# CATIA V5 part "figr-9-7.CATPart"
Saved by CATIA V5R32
Part number: Part2
Bounding box of the stored display mesh (mm): x -96.278 to 96.278, y -96.278 to 96.278, z -26.878 to 0
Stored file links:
  D:\PROJECTS\Project 2022\CATIA V5 6R 2022\Resources\Part Files\c09_catia_v5_6r2022_prt\c09_catia_v5_6r2022_prt\figr-9-7.CATPart
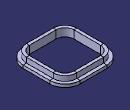
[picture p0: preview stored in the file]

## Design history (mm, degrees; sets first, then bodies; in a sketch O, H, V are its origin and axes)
Body1 (main body)
  Sketch1 on xy-plane, origin (0, 0, 0), H (1, 0, 0), V (0, 1, 0)
    point P1 (-75, 75)
    line L1 (-45, 75) -> (45, 75)
    line L2 (75, 45) -> (75, -45)
    line L3 (45, -75) -> (-45, -75)
    line L4 (-75, -45) -> (-75, 45)
    point P2 (75, 75)
    point P3 (75, -75)
    point P4 (-75, -75)
    axis line L5 (75, -75) -> (-75, 75)
    arc A1 centre (45, -45) radius 30 from (75, -45) to (45, -75) cw
    arc A2 centre (45, 45) radius 30 from (45, 75) to (75, 45) cw
    arc A3 centre (-45, 45) radius 30 from (-45, 75) to (-75, 45) ccw
    arc A4 centre (-45, -45) radius 30 from (-45, -75) to (-75, -45) cw
    distance P2 P3 = 150
    distance P3 P4 = 150
    radius A1 = 30
    radius A2 = 30
    radius A3 = 30
    radius A4 = 30
    horizontal: L1 H, L3 H
    vertical: L2 V, L4 V
    midpoint: O L5
    coincidence: L2 P3, L3 P3, L1 P2, L2 P2, L1 P1, L4 P1, L3 P4, L4 P4
    tangency: A1 L2, A1 L3, A2 L1, A2 L2, A3 L1, A3 L4, A4 L3, A4 L4
  Sketch2 on yz-plane, origin (0, 0, 0), H (0, 1, 0), V (0, 0, 1)
    point P1 (85, 0)
    line L1 (85, 0) -> (85, -16.8782)
    line L2 (85, -16.8782) -> (96.2781, -16.8782)
    line L3 (96.2781, -16.8782) -> (96.2781, -26.8782)
    line L4 (96.2781, -26.8782) -> (75, -26.8782)
    line L5 (75, -26.8782) -> (75, 0)
    point P6 (75, 0)
    line L6 (75, 0) -> (85, 0)
    reference projected point E1 (75, 0) from edge of Sketch1
    length L3 = 10
    length L6 = 10
    coincidence: P1 H, P6 H, P6 E1
    vertical: L1 V, L3 V, L5 V
    horizontal: L2 H, L4 H, L6 H
  Rib1: profile Sketch2, centre curve Sketch1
